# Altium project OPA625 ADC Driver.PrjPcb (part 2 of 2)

## Sheet OPA625 ADC Driver_OPA625 ADC Driver.SchDoc
size 762 x 381 mm; Date: Not shown in title block; ApprovedBy: Not shown in title block; CheckedBy: Not shown in title block; Author: Not shown in title block; CompanyName: Not shown in title block; Engineer: Not shown in title block; Organization: Not shown in title block; Address1: Not shown in title block; Address2: Not shown in title block; Address3: Not shown in title block; Address4: Not shown in title block; DocumentNumber: 5; Revision: Use project parameter SCH_Rev; SheetNumber: 5; SheetTotal: 8; PageSetup: Record=PageOptions¦CenterHorizontal=True¦CenterVertical=True¦PrintScale=1.00¦XCorrection=1.00¦YCorrection=1.00¦PrintKind=0¦BorderSize=5000000¦LeftOffset=0¦BottomOffset=0¦Orientation=2¦PaperLength=1000¦PaperWidth=1000¦Scale=100¦PaperSource=15¦PrintQuality=600¦MediaType=1¦DitherType=10¦PaperKind=Letter¦PrintScaleMode=1
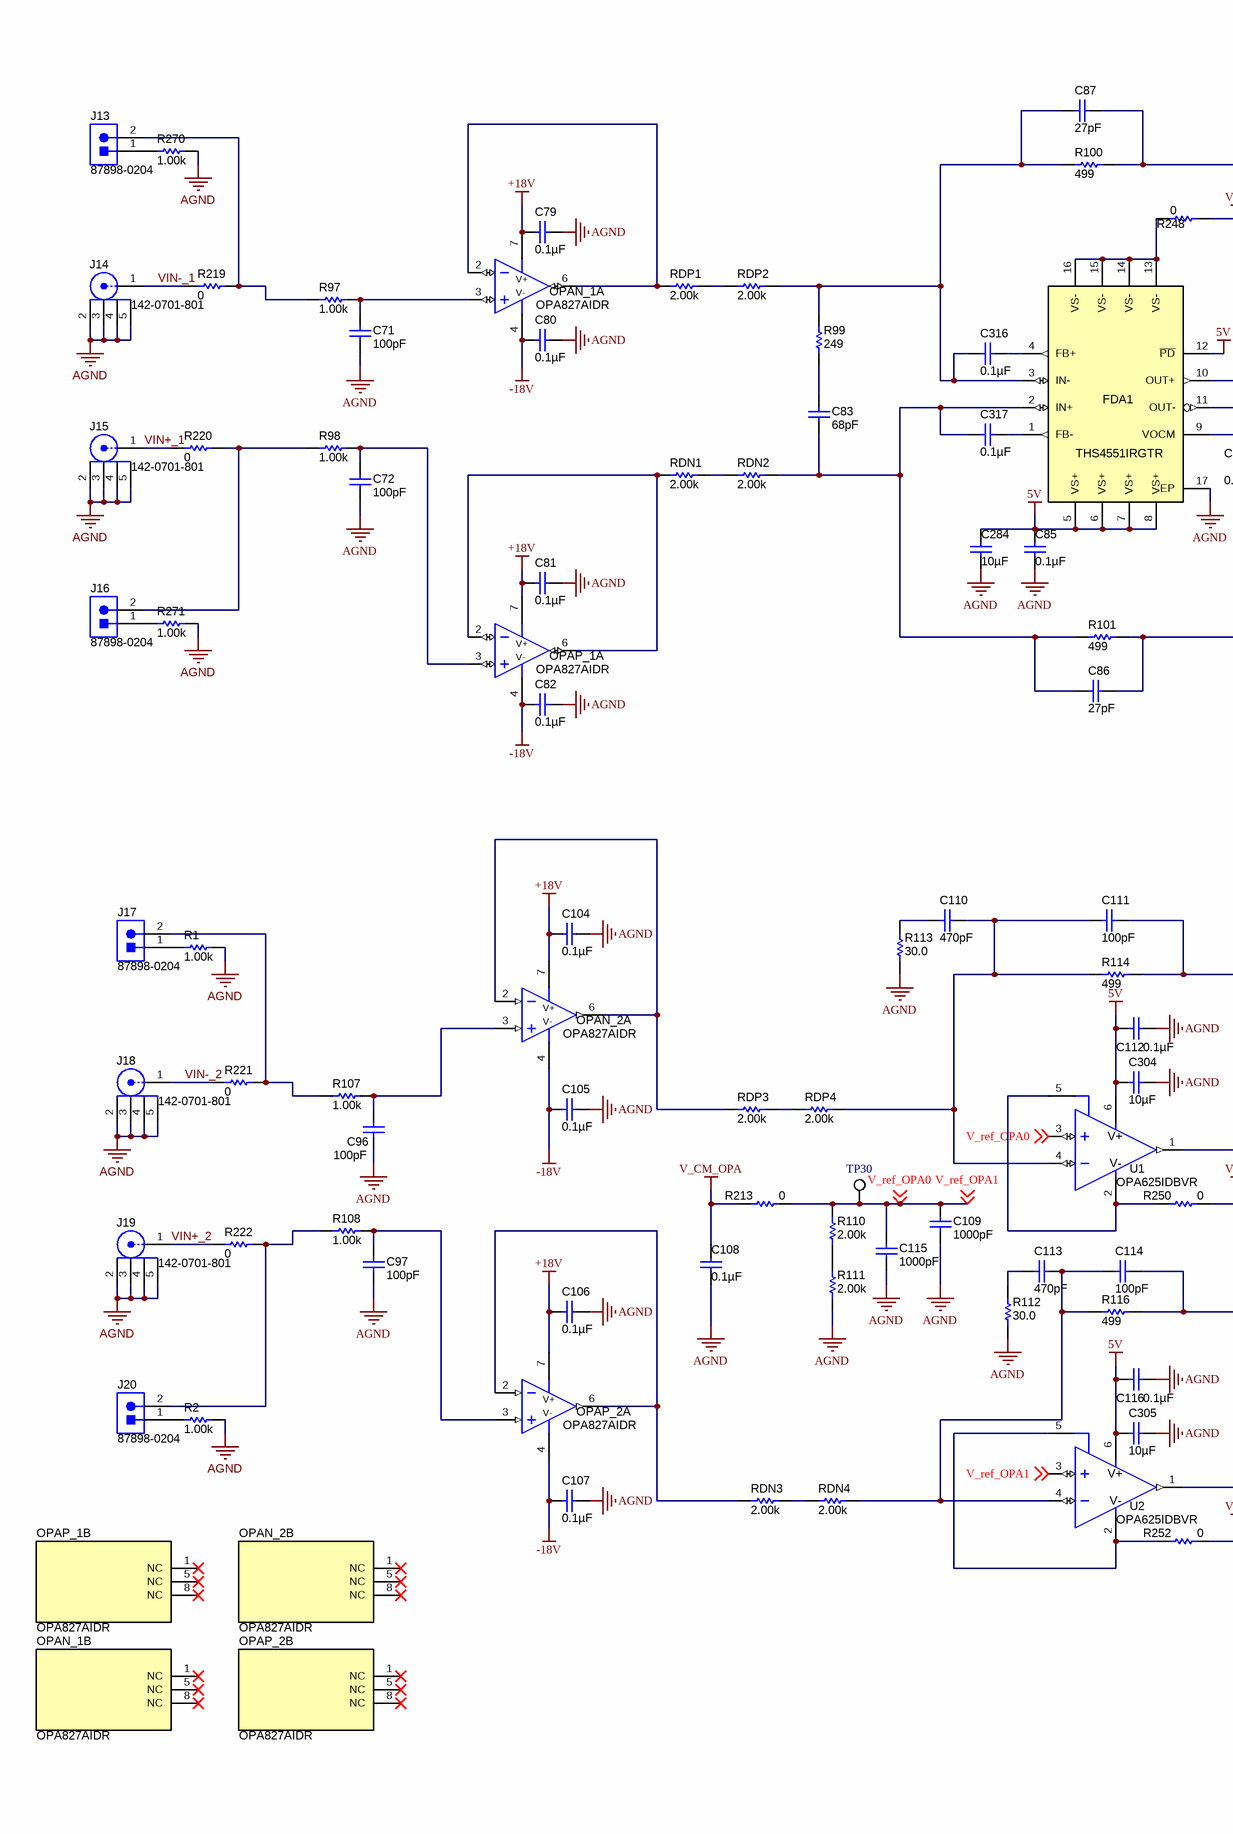
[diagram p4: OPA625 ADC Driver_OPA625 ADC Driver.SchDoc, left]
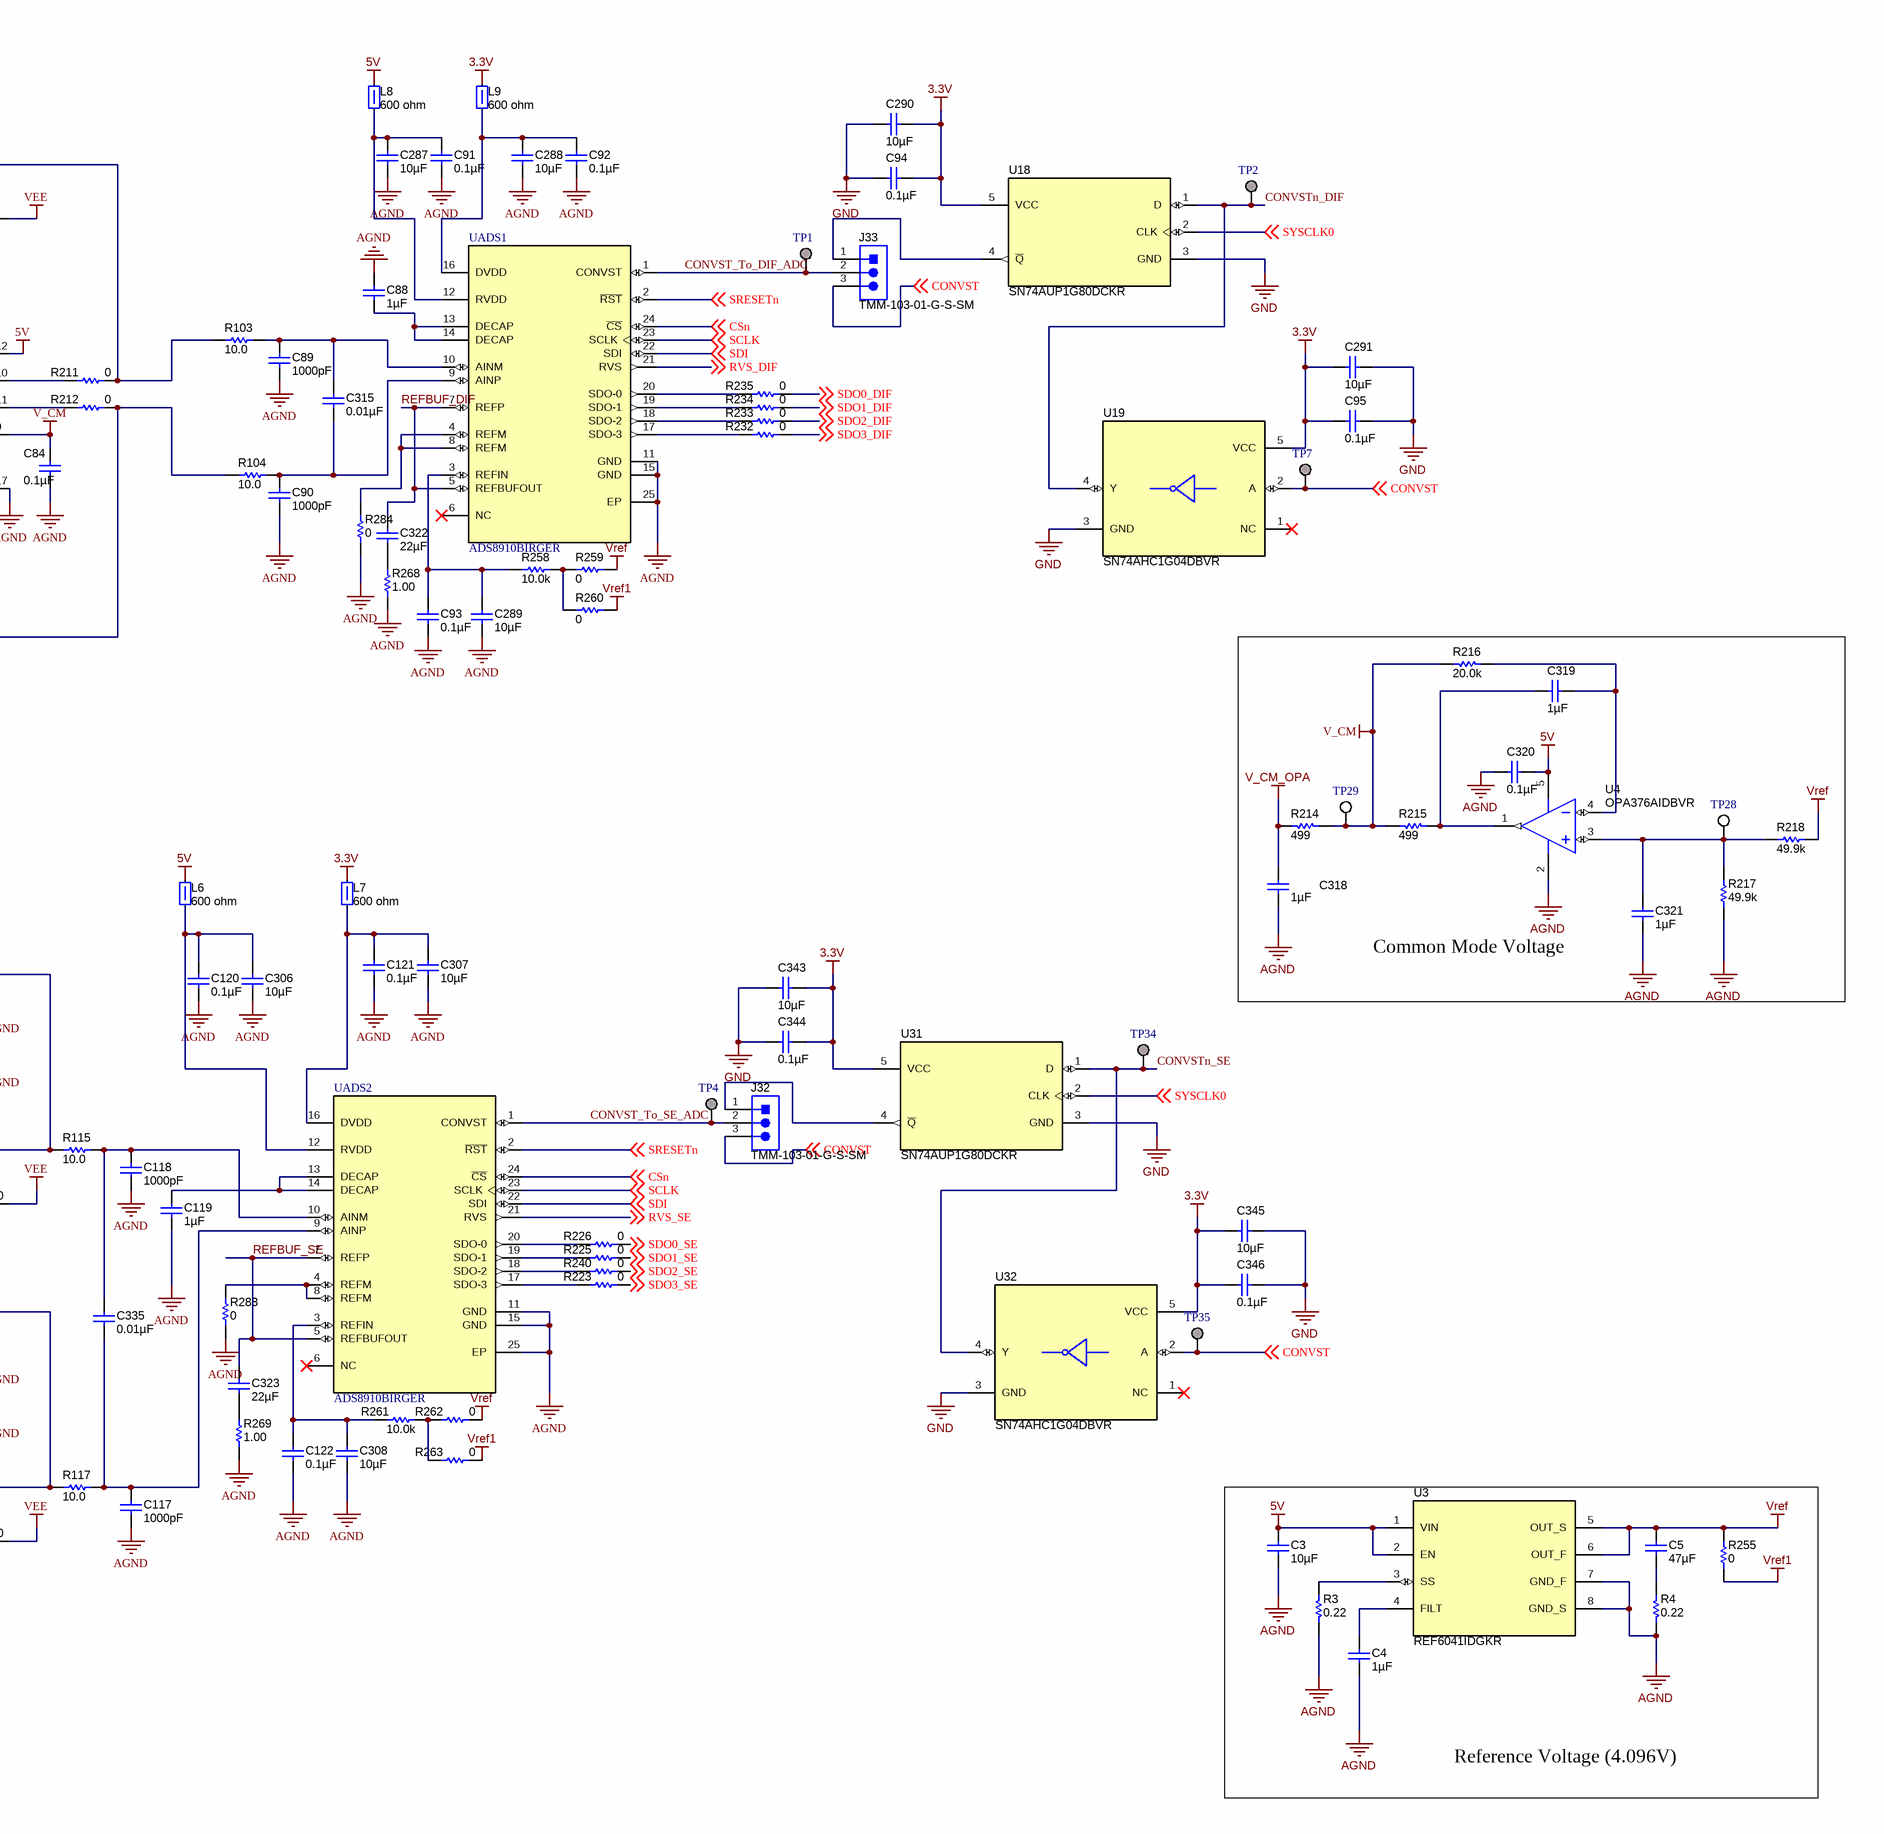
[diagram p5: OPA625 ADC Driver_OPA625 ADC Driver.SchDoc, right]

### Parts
C3  ValueDisplayed: 10µF  [0805]  (hidden comment: GRM21BR71A106KE51L)
C4  ValueDisplayed: 1µF  [0603]  (hidden comment: GRM188R71A105KA61D)
C5  ValueDisplayed: 47µF  [1210_270]  (hidden comment: GRM32ER71A476KE15L)
C71  ValueDisplayed: 100pF  [0603]  (hidden comment: GRM1885C1H101JA01D)
C72  ValueDisplayed: 100pF  [0603]  (hidden comment: GRM1885C1H101JA01D)
C79  ValueDisplayed: 0.1µF  [0603]  (hidden comment: GRM188R72A104KA35D)
C80  ValueDisplayed: 0.1µF  [0603]  (hidden comment: GRM188R72A104KA35D)
C81  ValueDisplayed: 0.1µF  [0603]  (hidden comment: GRM188R72A104KA35D)
C82  ValueDisplayed: 0.1µF  [0603]  (hidden comment: GRM188R72A104KA35D)
C83  ValueDisplayed: 68pF  [0603]  (hidden comment: C0603C680J5GACTU)
C84  ValueDisplayed: 0.1µF  [0603]  (hidden comment: C0603C104J3RACTU)
C85  ValueDisplayed: 0.1µF  [0603]  (hidden comment: C0603C104J3RACTU)
C86  ValueDisplayed: 27pF  [0603]  (hidden comment: C0603C270J5GACTU)
C87  ValueDisplayed: 27pF  [0603]  (hidden comment: C0603C270J5GACTU)
C88  ValueDisplayed: 1µF  [0603]  (hidden comment: GRM188R71A105KA61D)
C89  ValueDisplayed: 1000pF  [0603]  (hidden comment: C1608C0G2A102J080AA)
C90  ValueDisplayed: 1000pF  [0603]  (hidden comment: C1608C0G2A102J080AA)
C91  ValueDisplayed: 0.1µF  [0603]  (hidden comment: C0603C104J3RACTU)
C92  ValueDisplayed: 0.1µF  [0603]  (hidden comment: C0603C104J3RACTU)
C93  ValueDisplayed: 0.1µF  [0603]  (hidden comment: C0603C104J3RACTU)
C94  ValueDisplayed: 0.1µF  [0402]  (hidden comment: GRM155R71C104KA88D)
C95  ValueDisplayed: 0.1µF  [0402]  (hidden comment: GRM155R71C104KA88D)
C96  ValueDisplayed: 100pF  [0603]  (hidden comment: GRM1885C1H101JA01D)
C97  ValueDisplayed: 100pF  [0603]  (hidden comment: GRM1885C1H101JA01D)
C104  ValueDisplayed: 0.1µF  [0603]  (hidden comment: GRM188R72A104KA35D)
C105  ValueDisplayed: 0.1µF  [0603]  (hidden comment: GRM188R72A104KA35D)
C106  ValueDisplayed: 0.1µF  [0603]  (hidden comment: GRM188R72A104KA35D)
C107  ValueDisplayed: 0.1µF  [0603]  (hidden comment: GRM188R72A104KA35D)
C108  ValueDisplayed: 0.1µF  [0603]  (hidden comment: C0603C104J3RACTU)
C109  ValueDisplayed: 1000pF  [0603]  (hidden comment: C0603C102J5GAC)
C110  ValueDisplayed: 470pF  [0603]  (hidden comment: C0603C471K5RACTU)
C111  ValueDisplayed: 100pF  [0603]  (hidden comment: C0603C101J5GAC)
C112  ValueDisplayed: 0.1µF  [0603]  (hidden comment: C0603C104J3RACTU)
C113  ValueDisplayed: 470pF  [0603]  (hidden comment: C0603C471K5RACTU)
C114  ValueDisplayed: 100pF  [0603]  (hidden comment: C0603C101J5GAC)
C115  ValueDisplayed: 1000pF  [0603]  (hidden comment: C0603C102J5GAC)
C116  ValueDisplayed: 0.1µF  [0603]  (hidden comment: C0603C104J3RACTU)
C117  ValueDisplayed: 1000pF  [0603]  (hidden comment: C1608C0G2A102J080AA)
C118  ValueDisplayed: 1000pF  [0603]  (hidden comment: C1608C0G2A102J080AA)
C119  ValueDisplayed: 1µF  [0603]  (hidden comment: GRM188R71A105KA61D)
C120  ValueDisplayed: 0.1µF  [0603]  (hidden comment: C0603C104J3RACTU)
C121  ValueDisplayed: 0.1µF  [0603]  (hidden comment: C0603C104J3RACTU)
C122  ValueDisplayed: 0.1µF  [0603]  (hidden comment: C0603C104J3RACTU)
C284  ValueDisplayed: 10µF  [0805_HV]  (hidden comment: GRM21BR71A106KE51L)
C287  ValueDisplayed: 10µF  [0805_HV]  (hidden comment: GRM21BR71A106KE51L)
C288  ValueDisplayed: 10µF  [0805_HV]  (hidden comment: GRM21BR71A106KE51L)
C289  ValueDisplayed: 10µF  [0805_HV]  (hidden comment: GRM21BR71A106KE51L)
C290  ValueDisplayed: 10µF  [0805_HV]  (hidden comment: GRM21BR71A106KE51L)
C291  ValueDisplayed: 10µF  [0805_HV]  (hidden comment: GRM21BR71A106KE51L)
C304  ValueDisplayed: 10µF  [0805_HV]  (hidden comment: GRM21BR71A106KE51L)
C305  ValueDisplayed: 10µF  [0805_HV]  (hidden comment: GRM21BR71A106KE51L)
C306  ValueDisplayed: 10µF  [0805_HV]  (hidden comment: GRM21BR71A106KE51L)
C307  ValueDisplayed: 10µF  [0805_HV]  (hidden comment: GRM21BR71A106KE51L)
C308  ValueDisplayed: 10µF  [0805_HV]  (hidden comment: GRM21BR71A106KE51L)
C315  ValueDisplayed: 0.01µF  [0603]  (hidden comment: CGA3E2C0G1H103J080AA)
C316  ValueDisplayed: 0.1µF  [0603]  (hidden comment: C0603C104J3RACTU)
C317  ValueDisplayed: 0.1µF  [0603]  (hidden comment: C0603C104J3RACTU)
C318  ValueDisplayed: 1µF  [0603]  (hidden comment: GRM188R71E105KA12D)
C319  ValueDisplayed: 1µF  [0603]  (hidden comment: GRM188R71E105KA12D)
C320  ValueDisplayed: 0.1µF  [0603]  (hidden comment: C0603C104J3RACTU)
C321  ValueDisplayed: 1µF  [0603]  (hidden comment: GRM188R71E105KA12D)
C322  ValueDisplayed: 22µF  [0603]  (hidden comment: C1608X5R1A226M080AC)
C323  ValueDisplayed: 22µF  [0603]  (hidden comment: C1608X5R1A226M080AC)
C335  ValueDisplayed: 0.01µF  [0603]  (hidden comment: CGA3E2C0G1H103J080AA)
C343  ValueDisplayed: 10µF  [0805_HV]  (hidden comment: GRM21BR71A106KE51L)
C344  ValueDisplayed: 0.1µF  [0402]  (hidden comment: GRM155R71C104KA88D)
C345  ValueDisplayed: 10µF  [0805_HV]  (hidden comment: GRM21BR71A106KE51L)
C346  ValueDisplayed: 0.1µF  [0402]  (hidden comment: GRM155R71C104KA88D)
FDA1  THS4551IRGTR  [RGT0016A]
J13  87898-0204  [Molex_87898-0204]
J14  142-0701-801  [JOHNSON_142-0701-801]
J15  142-0701-801  [JOHNSON_142-0701-801]
J16  87898-0204  [Molex_87898-0204]
J17  87898-0204  [Molex_87898-0204]
J18  142-0701-801  [JOHNSON_142-0701-801]
J19  142-0701-801  [JOHNSON_142-0701-801]
J20  87898-0204  [Molex_87898-0204]
J32  TMM-103-01-G-S-SM  [Samtec_TMM-103-01-x-S-SM]
J33  TMM-103-01-G-S-SM  [Samtec_TMM-103-01-x-S-SM]
L6  value 600 ohm  [0805_HV]  (hidden comment: MPZ2012S601A)
L7  value 600 ohm  [0805_HV]  (hidden comment: MPZ2012S601A)
L8  value 600 ohm  [0805_HV]  (hidden comment: MPZ2012S601A)
L9  value 600 ohm  [0805_HV]  (hidden comment: MPZ2012S601A)
OPAN_1  OPA827AIDR  [D0008A_N]  (parts A,B of 2)
OPAN_2  OPA827AIDR  [D0008A_N]  (parts A,B of 2)
OPAP_1  OPA827AIDR  [D0008A_N]  (parts A,B of 2)
OPAP_2  OPA827AIDR  [D0008A_N]  (parts A,B of 2)
R1  ValueDisplayed: 1.00k  [0603]  (hidden comment: RG1608P-102-B-T5)
R2  ValueDisplayed: 1.00k  [0603]  (hidden comment: RG1608P-102-B-T5)
R3  value 0.22  [0603]  (hidden comment: ERJ-3RQFR22V)
R4  value 0.22  [0603]  (hidden comment: ERJ-3RQFR22V)
R97  ValueDisplayed: 1.00k  [0603]  (hidden comment: RG1608P-102-B-T5)
R98  ValueDisplayed: 1.00k  [0603]  (hidden comment: RG1608P-102-B-T5)
R99  ValueDisplayed: 249  [0603]  (hidden comment: CRCW0603249RFKEA)
R100  ValueDisplayed: 499  [0603]  (hidden comment: RC0603FR-07499RL)
R101  ValueDisplayed: 499  [0603]  (hidden comment: RC0603FR-07499RL)
R103  ValueDisplayed: 10.0  [0603]  (hidden comment: RT0603BRD0710RL)
R104  ValueDisplayed: 10.0  [0603]  (hidden comment: RT0603BRD0710RL)
R107  ValueDisplayed: 1.00k  [0603]  (hidden comment: RG1608P-102-B-T5)
R108  ValueDisplayed: 1.00k  [0603]  (hidden comment: RG1608P-102-B-T5)
R110  ValueDisplayed: 2.00k  [0603]  (hidden comment: RG1608P-202-B-T5)
R111  ValueDisplayed: 2.00k  [0603]  (hidden comment: RG1608P-202-B-T5)
R112  ValueDisplayed: 30.0  [0603]  (hidden comment: RC0603FR-0730RL)
R113  ValueDisplayed: 30.0  [0603]  (hidden comment: RC0603FR-0730RL)
R114  ValueDisplayed: 499  [0603]  (hidden comment: RC0603FR-07499RL)
R115  ValueDisplayed: 10.0  [0603]  (hidden comment: RT0603BRD0710RL)
R116  ValueDisplayed: 499  [0603]  (hidden comment: RC0603FR-07499RL)
R117  ValueDisplayed: 10.0  [0603]  (hidden comment: RT0603BRD0710RL)
R211  ValueDisplayed: 0  [0402]  (hidden comment: ERJ-2GE0R00X)
R212  ValueDisplayed: 0  [0402]  (hidden comment: ERJ-2GE0R00X)
R213  ValueDisplayed: 0  [0402]  (hidden comment: ERJ-2GE0R00X)
R214  ValueDisplayed: 499  [0603]  (hidden comment: RG1608P-4990-B-T5)
R215  ValueDisplayed: 499  [0603]  (hidden comment: RG1608P-4990-B-T5)
R216  ValueDisplayed: 20.0k  [0603]  (hidden comment: RG1608P-203-B-T5)
R217  ValueDisplayed: 49.9k  [0603]  (hidden comment: RG1608P-4992-B-T5)
R218  ValueDisplayed: 49.9k  [0603]  (hidden comment: RG1608P-4992-B-T5)
R219  ValueDisplayed: 0  [0603]  (hidden comment: ERJ-3GEY0R00V)
R220  ValueDisplayed: 0  [0603]  (hidden comment: ERJ-3GEY0R00V)
R221  ValueDisplayed: 0  [0603]  (hidden comment: ERJ-3GEY0R00V)
R222  ValueDisplayed: 0  [0603]  (hidden comment: ERJ-3GEY0R00V)
R223  ValueDisplayed: 0  [0402]  (hidden comment: ERJ-2GE0R00X)
R225  ValueDisplayed: 0  [0402]  (hidden comment: ERJ-2GE0R00X)
R226  ValueDisplayed: 0  [0402]  (hidden comment: ERJ-2GE0R00X)
R232  ValueDisplayed: 0  [0402]  (hidden comment: ERJ-2GE0R00X)
R233  ValueDisplayed: 0  [0402]  (hidden comment: ERJ-2GE0R00X)
R234  ValueDisplayed: 0  [0402]  (hidden comment: ERJ-2GE0R00X)
R235  ValueDisplayed: 0  [0402]  (hidden comment: ERJ-2GE0R00X)
R240  ValueDisplayed: 0  [0402]  (hidden comment: ERJ-2GE0R00X)
R248  ValueDisplayed: 0  [0402]  (hidden comment: ERJ-2GE0R00X)
R250  ValueDisplayed: 0  [0402]  (hidden comment: ERJ-2GE0R00X)
R252  ValueDisplayed: 0  [0402]  (hidden comment: ERJ-2GE0R00X)
R255  ValueDisplayed: 0  [0402]  (hidden comment: ERJ-2GE0R00X)
R258  ValueDisplayed: 10.0k  [0603]  (hidden comment: RG1608P-103-B-T5)
R259  ValueDisplayed: 0  [0402]  (hidden comment: ERJ-2GE0R00X)
R260  ValueDisplayed: 0  [0402]  (hidden comment: ERJ-2GE0R00X)
R261  ValueDisplayed: 10.0k  [0603]  (hidden comment: RG1608P-103-B-T5)
R262  ValueDisplayed: 0  [0402]  (hidden comment: ERJ-2GE0R00X)
R263  ValueDisplayed: 0  [0402]  (hidden comment: ERJ-2GE0R00X)
R268  ValueDisplayed: 1.00  [0603]  (hidden comment: CRCW06031R00FKEA)
R269  ValueDisplayed: 1.00  [0603]  (hidden comment: CRCW06031R00FKEA)
R270  ValueDisplayed: 1.00k  [0603]  (hidden comment: RG1608P-102-B-T5)
R271  ValueDisplayed: 1.00k  [0603]  (hidden comment: RG1608P-102-B-T5)
R284  ValueDisplayed: 0  [0402]  (hidden comment: ERJ-2GE0R00X)
R288  ValueDisplayed: 0  [0402]  (hidden comment: ERJ-2GE0R00X)
RDN1  ValueDisplayed: 2.00k  [0603]  (hidden comment: RG1608P-202-B-T5)
RDN2  ValueDisplayed: 2.00k  [0603]  (hidden comment: RG1608P-202-B-T5)
RDN3  ValueDisplayed: 2.00k  [0603]  (hidden comment: RG1608P-202-B-T5)
RDN4  ValueDisplayed: 2.00k  [0603]  (hidden comment: RG1608P-202-B-T5)
RDP1  ValueDisplayed: 2.00k  [0603]  (hidden comment: RG1608P-202-B-T5)
RDP2  ValueDisplayed: 2.00k  [0603]  (hidden comment: RG1608P-202-B-T5)
RDP3  ValueDisplayed: 2.00k  [0603]  (hidden comment: RG1608P-202-B-T5)
RDP4  ValueDisplayed: 2.00k  [0603]  (hidden comment: RG1608P-202-B-T5)
TP1  Pogo Pad  [PogoPad]  (value not drawn)  (no BOM)
TP2  Pogo Pad  [PogoPad]  (value not drawn)  (no BOM)
TP4  Pogo Pad  [PogoPad]  (value not drawn)  (no BOM)
TP7  Pogo Pad  [PogoPad]  (value not drawn)  (no BOM)
TP28  5015  [Testpoint_Keystone_Miniature]  (value not drawn)
TP29  5015  [Testpoint_Keystone_Miniature]  (value not drawn)
TP30  5015  [Testpoint_Keystone_Miniature]  (value not drawn)
TP34  Pogo Pad  [PogoPad]  (value not drawn)  (no BOM)
TP35  Pogo Pad  [PogoPad]  (value not drawn)  (no BOM)
U1  OPA625IDBVR  [DBV0006A_N]
U2  OPA625IDBVR  [DBV0006A_N]
U3  REF6041IDGKR  [DGK0008A_N]
U4  OPA376AIDBVR  [DBV0005A_N]
U18  SN74AUP1G80DCKR  [DCK0005A_N]
U19  SN74AHC1G04DBVR  [DBV0005A_N]
U31  SN74AUP1G80DCKR  [DCK0005A_N]
U32  SN74AHC1G04DBVR  [DBV0005A_N]
UADS1  ADS8910BIRGER  [RGE0024H]
UADS2  ADS8910BIRGER  [RGE0024H]

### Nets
3.3V: C94.2 C95.2 C290.1 C291.2 C343.1 C344.2 C345.2 C346.2 L7.1 L9.1 U18.5(VCC) U19.5(VCC) U31.5(VCC) U32.5(VCC)
5V: C3.2 C85.1 C112.2 C116.2 C284.1 C304.1 C305.1 C320.2 FDA1.5(VS+) FDA1.6(VS+) FDA1.7(VS+) FDA1.8(VS+) FDA1.12(~{PD}) L6.1 L8.1 U1.6(V+) U2.6(V+) U3.1(VIN) U3.2(EN) U4.5(V+)
+18V: C79.2 C81.2 C104.2 C106.2 OPAN_1.7(V+) OPAN_2.7(V+) OPAP_1.7(V+) OPAP_2.7(V+)
-18V: C80.2 C82.2 C105.2 C107.2 OPAN_1.4(V-) OPAN_2.4(V-) OPAP_1.4(V-) OPAP_2.4(V-)
AGND: C3.1 C4.2 C71.1 C72.1 C79.1 C80.1 C81.1 C82.1 C84.2 C85.2 C88.1 C89.2 C90.2 C91.1 C92.2 C93.2 C96.1 C97.1 C104.1 C105.1 C106.1 C107.1 C108.2 C109.2 C112.1 C115.2 C116.1 C117.2 C118.2 C119.2 C120.1 C121.2 C122.2 C284.2 C287.2 C288.2 C289.2 C304.2 C305.2 C306.2 C307.2 C308.2 C318.2 C320.1 C321.2 FDA1.17(EP) J14.2 J14.3 J14.4 J14.5 J15.2 J15.3 J15.4 J15.5 J18.2 J18.3 J18.4 J18.5 J19.2 J19.3 J19.4 J19.5 R1.2 R2.2 R3.1 R4.2 R111.1 R112.1 R113.1 R217.1 R268.1 R269.1 R270.2 R271.2 R284.1 R288.1 U3.7(GND_F) U3.8(GND_S) U4.2(V-) UADS1.11(GND) UADS1.15(GND) UADS1.25(EP) UADS2.11(GND) UADS2.15(GND) UADS2.25(EP)
GND: C94.1 C95.1 C290.2 C291.1 C343.2 C344.1 C345.1 C346.1 U18.3(GND) U19.3(GND) U31.3(GND) U32.3(GND)
V_CM: C84.1 FDA1.9(VOCM) R214.1 R215.2 R216.2 TP29.1
V_CM_OPA: C108.1 C318.1 R213.1 R214.2
VEE: R248.2 R250.2 R252.2
Vref: C5.1 R218.2 R255.2 R259.1 R262.2 U3.5(OUT_S) U3.6(OUT_F)
Vref1: R255.1 R260.1 R263.2
CONVST: J32.3 J33.3 TP7.1 TP35.1 U19.2(A) U32.2(A) ; off-sheet CONVST
CONVST_To_DIF_ADC: J33.2 TP1.1 UADS1.1(CONVST)
CONVST_To_SE_ADC: J32.2 TP4.1 UADS2.1(CONVST)
CONVSTn_DIF: TP2.1 U18.1(D) U19.4(Y)
CONVSTn_SE: TP34.1 U31.1(D) U32.4(Y)
CSn: UADS1.24(~{CS}) UADS2.24(~{CS}) ; off-sheet CSn
REFBUF_DIF: C322.1 UADS1.5(REFBUFOUT) UADS1.7(REFP)
REFBUF_SE: C323.1 UADS2.5(REFBUFOUT) UADS2.7(REFP)
RVS_DIF: UADS1.21(RVS) ; off-sheet RVS_DIF
RVS_SE: UADS2.21(RVS) ; off-sheet RVS_SE
SCLK: UADS1.23(SCLK) UADS2.23(SCLK) ; off-sheet SCLK
SDI: UADS1.22(SDI) UADS2.22(SDI) ; off-sheet SDI
SDO0_DIF: R235.2 ; off-sheet SDO0_DIF
SDO0_SE: R226.2 ; off-sheet SDO0_SE
SDO1_DIF: R234.2 ; off-sheet SDO1_DIF
SDO1_SE: R225.2 ; off-sheet SDO1_SE
SDO2_DIF: R233.2 ; off-sheet SDO2_DIF
SDO2_SE: R240.2 ; off-sheet SDO2_SE
SDO3_DIF: R232.2 ; off-sheet SDO3_DIF
SDO3_SE: R223.2 ; off-sheet SDO3_SE
SRESETn: UADS1.2(~{RST}) UADS2.2(~{RST}) ; off-sheet SRESETn
SYSCLK0: U18.2(CLK) U31.2(CLK) ; off-sheet SYSCLK0
V_ref_OPA0: C109.1 C115.1 R110.2 R213.2 TP30.1 U1.3(IN+) U2.3(IN+) ; off-sheet V_ref_OPA0, off-sheet V_ref_OPA1  [also labelled V_ref_OPA1]
VIN+_1: J15.1 R220.1
VIN+_2: J19.1 R222.1
VIN-_1: J14.1 R219.1
VIN-_2: J18.1 R221.1
NetC4_1: C4.1 U3.4(FILT)
NetC5_2: C5.2 R4.1
NetC71_2: C71.2 OPAN_1.3(IN+) R97.2
NetC72_2: C72.2 OPAP_1.3(IN+) R98.2
NetC83_1: C83.1 R99.1
NetC83_2: C83.2 C86.2 C317.2 FDA1.2(IN+) R101.1 RDN2.2
NetC86_1: C86.1 R101.2 R104.1 R212.2
NetC87_1: C87.1 R100.2 R103.1 R211.2
NetC87_2: C87.2 C316.2 FDA1.3(IN-) R99.2 R100.1 RDP2.2
NetC88_2: C88.2 UADS1.13(DECAP) UADS1.14(DECAP)
NetC89_1: C89.1 C315.1 R103.2 UADS1.10(AINM)
NetC90_1: C90.1 C315.2 R104.2 UADS1.9(AINP)
NetC91_2: C91.2 C287.1 L8.2 UADS1.12(RVDD)
NetC92_1: C92.1 C288.1 L9.2 UADS1.16(DVDD)
NetC93_1: C93.1 C289.1 R258.1 UADS1.3(REFIN)
NetC96_2: C96.2 OPAN_2.3(IN+) R107.2
NetC97_2: C97.2 OPAP_2.3(IN+) R108.2
NetC110_1: C110.1 R113.2
NetC110_2: C110.2 C111.2 R114.1 RDP4.2 U1.4(IN-)
NetC111_1: C111.1 R114.2 R115.1 U1.1(OUT)
NetC113_1: C113.1 C114.2 R116.1 RDN4.2 U2.4(IN-)
NetC113_2: C113.2 R112.2
NetC114_1: C114.1 R116.2 R117.1 U2.1(OUT)
NetC117_1: C117.1 C335.2 R117.2 UADS2.9(AINP)
NetC118_1: C118.1 C335.1 R115.2 UADS2.10(AINM)
NetC119_1: C119.1 UADS2.13(DECAP) UADS2.14(DECAP)
NetC120_2: C120.2 C306.1 L6.2 UADS2.12(RVDD)
NetC121_1: C121.1 C307.1 L7.2 UADS2.16(DVDD)
NetC122_1: C122.1 C308.1 R261.1 UADS2.3(REFIN)
NetC316_1: C316.1 FDA1.4(FB+)
NetC317_1: C317.1 FDA1.1(FB-)
NetC319_1: C319.1 R215.1 U4.1(OUT)
NetC319_2: C319.2 R216.1 U4.4(IN-)
NetC321_1: C321.1 R217.2 R218.1 TP28.1 U4.3(IN+)
NetC322_2: C322.2 R268.2
NetC323_2: C323.2 R269.2
NetFDA1_10: FDA1.10(OUT+) R211.1
NetFDA1_11: FDA1.11(OUT-) R212.1
NetFDA1_13: FDA1.13(VS-) FDA1.14(VS-) FDA1.15(VS-) FDA1.16(VS-) R248.1
NetJ13_1: J13.1 R270.1
NetJ13_2: J13.2 R97.1 R219.2
NetJ16_1: J16.1 R271.1
NetJ16_2: J16.2 R98.1 R220.2
NetJ17_1: J17.1 R1.1
NetJ17_2: J17.2 R107.1 R221.2
NetJ20_1: J20.1 R2.1
NetJ20_2: J20.2 R108.1 R222.2
NetJ32_1: J32.1 U31.4(~{Q})
NetJ33_1: J33.1 U18.4(~{Q})
NetOPAN_1_2: OPAN_1.2(IN-) OPAN_1.6(OUT) RDP1.1
NetOPAN_2_2: OPAN_2.2(IN-) OPAN_2.6(OUT) RDP3.1
NetOPAP_1_2: OPAP_1.2(IN-) OPAP_1.6(OUT) RDN1.1
NetOPAP_2_2: OPAP_2.2(IN-) OPAP_2.6(OUT) RDN3.1
NetR3_2: R3.2 U3.3(SS)
NetR110_1: R110.1 R111.2
NetR223_1: R223.1 UADS2.17(SDO-3)
NetR225_1: R225.1 UADS2.19(SDO-1)
NetR226_1: R226.1 UADS2.20(SDO-0)
NetR232_1: R232.1 UADS1.17(SDO-3)
NetR233_1: R233.1 UADS1.18(SDO-2)
NetR234_1: R234.1 UADS1.19(SDO-1)
NetR235_1: R235.1 UADS1.20(SDO-0)
NetR240_1: R240.1 UADS2.18(SDO-2)
NetR250_1: R250.1 U1.2(V-) U1.5(MODE)
NetR252_1: R252.1 U2.2(V-) U2.5(MODE)
NetR258_2: R258.2 R259.2 R260.2
NetR261_2: R261.2 R262.1 R263.1
NetR284_2: R284.2 UADS1.4(REFM) UADS1.8(REFM)
NetR288_2: R288.2 UADS2.4(REFM) UADS2.8(REFM)
NetRDN1_2: RDN1.2 RDN2.1
NetRDN3_2: RDN3.2 RDN4.1
NetRDP1_2: RDP1.2 RDP2.1
NetRDP3_2: RDP3.2 RDP4.1

Not connected (* = marked no-connect by the designer): OPAN_1 1(NC)* 5(NC)* 8(NC)*; OPAN_2 1(NC)* 5(NC)* 8(NC)*; OPAP_1 1(NC)* 5(NC)* 8(NC)*; OPAP_2 1(NC)* 5(NC)* 8(NC)*; U19 1(NC)*; U32 1(NC)*; UADS1 6(NC)*; UADS2 6(NC)*

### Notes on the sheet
- Common Mode Voltage
- Reference Voltage (4.096V)

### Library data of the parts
C3 = GRM21BR71A106KE51L: CAP, CERM, 10uF, 10V, +/-10%, X7R, 0805; Manufacturer: MuRata; Polarized: N; CompType: Capacitor; U/M: EA; Cap_F: 0.00001; Tolerance_%: 10; ESR_Ohm: 0.003; Value1: 0.003 ohm; TaMin_C: -55; TaMax_C: 125
C4 = GRM188R71A105KA61D: CAP, CERM, 1uF, 10V, +/-10%, X7R, 0603; Manufacturer: MuRata; Polarized: N; CompType: Capacitor; U/M: EA; Cap_F: 0.000001; Tolerance_%: 10; ESR_Ohm: 0.011; Value1: 0.011 ohm; TaMin_C: -55; TaMax_C: 125
C5 = GRM32ER71A476KE15L: CAP, CERM, 47 µF, 10 V, +/- 10%, X7R, 1210; Manufacturer: MuRata; Polarized: N; CompType: Capacitor; Value: 47uF; U/M: EA; Cap_F: 0.000047; Tolerance_%: 10; Value1: Unknown; Value2: 10V; TaMin_C: -55; TaMax_C: 125; Cap_Case: 1210; SizeArea_mm2: 8; SizeAreaWB_mm2: 14.7; SizeX_mm: 3.2; SizeY_mm: 2.5; SizeZ_mm: 2.7; AEC Category: Q200
C71 C72 C96 C97 = GRM1885C1H101JA01D: CAP, CERM, 100 pF, 50 V, +/- 5%, C0G/NP0, 0603; Manufacturer: MuRata; Polarized: N; CompType: Capacitor; Value: 100pF; U/M: EA; Cap_F: 0.0000000001; Tolerance_%: 5; Value1: Unknown; VDC_V: 50; Value2: 50V; TaMin_C: -55; TaMax_C: 125; AEC Category: Q200
C79-C82 C104-C107 = GRM188R72A104KA35D: CAP, CERM, 0.1 µF, 100 V, +/- 10%, X7R, 0603; Manufacturer: MuRata; Polarized: N; CompType: Capacitor; Value: 0.1uF; U/M: EA; Cap_F: 0.0000001; Tolerance_%: 10; Value1: Unknown; VDC_V: 100; Value2: 100V; TaMin_C: -55; TaMax_C: 125; SizeArea_mm2: 1.28; SizeAreaWB_mm2: 4.68; SizeX_mm: 1.6; SizeY_mm: 0.8; SizeZ_mm: 1; AEC Category: Q200
C83 = C0603C680J5GACTU: CAP, CERM, 68 pF, 50 V, +/- 5%, C0G/NP0, 0603; Manufacturer: Kemet; Polarized: N; CompType: Capacitor; Value: 68pF; U/M: EA; Cap_F: 0.000000000068; Tolerance_%: 5; Value1: Unknown; VDC_V: 50; Value2: 50V; TaMin_C: -55; TaMax_C: 125; SizeArea_mm2: 1.28; SizeAreaWB_mm2: 4.68; SizeX_mm: 1.6; SizeY_mm: 0.8; SizeZ_mm: 1; AEC Category: Q200
C84 C85 C91-C93 C108 C112 C116 C120-C122 C316 C317 = C0603C104J3RACTU: CAP, CERM, 0.1 µF, 25 V, +/- 5%, X7R, 0603; Manufacturer: Kemet; Polarized: N; CompType: Capacitor; Value: 0.1uF; U/M: EA; Cap_F: 0.0000001; Tolerance_%: 5; Value1: Unknown; VDC_V: 25; Value2: 25V; TaMin_C: -55; TaMax_C: 125
C86 C87 = C0603C270J5GACTU: CAP, CERM, 27 pF, 50 V, +/- 5%, C0G/NP0, 0603; Manufacturer: Kemet; Polarized: N; CompType: Capacitor; Value: 27pF; U/M: EA; Cap_F: 0.000000000027; Tolerance_%: 5; Value1: Unknown; VDC_V: 50; Value2: 50V; TaMin_C: -55; TaMax_C: 125; SizeArea_mm2: 1.28; SizeAreaWB_mm2: 4.68; SizeX_mm: 1.6; SizeY_mm: 0.8; SizeZ_mm: 1; AEC Category: Q200
C88 C119 = GRM188R71A105KA61D: CAP, CERM, 1 µF, 10 V, +/- 10%, X7R, 0603; Manufacturer: MuRata; Polarized: N; CompType: Capacitor; Value: 1uF; U/M: EA; Cap_F: 0.000001; Tolerance_%: 10; ESR_ohm: 0.011; Value1: 0.011 ohm; Value2: 10V; TaMin_C: -55; TaMax_C: 125; SizeArea_mm2: 1.28; SizeAreaWB_mm2: 4.68; SizeX_mm: 1.6; SizeY_mm: 0.8; SizeZ_mm: 1; AEC Category: Q200
C89 C90 C117 C118 = C1608C0G2A102J080AA: CAP, CERM, 1000 pF, 100 V, +/- 5%, C0G/NP0, 0603; Manufacturer: TDK; Polarized: N; CompType: Capacitor; Value: 1000pF; U/M: EA; Cap_F: 0.000000001; Tolerance_%: 5; ESR_ohm: 0.0589; Value1: 0.0589 ohm; VDC_V: 100; Value2: 100V; TaMin_C: -55; TaMax_C: 125; SizeArea_mm2: 1.28; SizeAreaWB_mm2: 4.68; SizeX_mm: 1.6; SizeY_mm: 0.8; SizeZ_mm: 1; AEC Category: Q200
C94 C95 C344 C346 = GRM155R71C104KA88D: CAP, CERM, 0.1 µF, 16 V, +/- 10%, X7R, 0402; Manufacturer: MuRata; Polarized: N; CompType: Capacitor; Value: 0.1uF; U/M: EA; Cap_F: 0.0000001; Tolerance_%: 10; Value1: Unknown; VDC_V: 16; Value2: 16V; TaMin_C: -55; TaMax_C: 125
C109 C115 = C0603C102J5GAC: CAP, CERM, 1000 pF, 50 V, +/- 5%, C0G/NP0, 0603; Manufacturer: Kemet; Polarized: N; CompType: Capacitor; Value: 1000pF; U/M: EA; Cap_F: 0.000000001; Tolerance_%: 5; Value1: Unknown; VDC_V: 50; Value2: 50V; TaMin_C: -55; TaMax_C: 125; SizeArea_mm2: 1.28; SizeAreaWB_mm2: 4.68; SizeX_mm: 1.6; SizeY_mm: 0.8; SizeZ_mm: 1; AEC Category: Q200
C110 C113 = C0603C471K5RACTU: CAP, CERM, 470 pF, 50 V, +/- 10%, X7R, 0603; Manufacturer: Kemet; Polarized: N; CompType: Capacitor; Value: 470pF; U/M: EA; Cap_F: 0.00000000047; Tolerance_%: 10; Value1: Unknown; VDC_V: 50; Value2: 50V; TaMin_C: -55; TaMax_C: 125; SizeArea_mm2: 1.28; SizeAreaWB_mm2: 4.68; SizeX_mm: 1.6; SizeY_mm: 0.8; SizeZ_mm: 1; AEC Category: Q200
C111 C114 = C0603C101J5GAC: CAP, CERM, 100 pF, 50 V, +/- 5%, C0G/NP0, 0603; Manufacturer: Kemet; Polarized: N; CompType: Capacitor; Value: 100pF; U/M: EA; Cap_F: 0.0000000001; Tolerance_%: 5; Value1: Unknown; VDC_V: 50; Value2: 50V; TaMin_C: -55; TaMax_C: 125; SizeArea_mm2: 1.28; SizeAreaWB_mm2: 4.68; SizeX_mm: 1.6; SizeY_mm: 0.8; SizeZ_mm: 1; AEC Category: Q200
C284 C287-C291 C304-C308 C343 C345 = GRM21BR71A106KE51L: CAP, CERM, 10 µF, 10 V, +/- 10%, X7R, 0805; Manufacturer: MuRata; Polarized: N; CompType: Capacitor; Value: 10uF; U/M: EA; Cap_F: 0.00001; Tolerance_%: 10; ESR_ohm: 0.003; Value1: 0.003 ohm; Value2: 10V; TaMin_C: -55; TaMax_C: 125; Cap_Case: 0805; AEC Category: Q200
C315 C335 = CGA3E2C0G1H103J080AA: CAP, CERM, 0.01 µF, 50 V, +/- 5%, C0G/NP0, AEC-Q200 Grade 1, 0603; Manufacturer: TDK; Polarized: N; CompType: Capacitor; Value: 0.01uF; U/M: EA; Cap_F: 0.00000001; Tolerance_%: 5; Value1: Unknown; VDC_V: 50; Value2: 50V; TaMin_C: -55; TaMax_C: 125; SizeArea_mm2: 1.28; SizeAreaWB_mm2: 4.68; SizeX_mm: 1.6; SizeY_mm: 0.8; SizeZ_mm: 1; AEC Category: Q200; AEC Qualified: Y
C318 C319 C321 = GRM188R71E105KA12D: CAP, CERM, 1 µF, 25 V, +/- 10%, X7R, 0603; Manufacturer: MuRata; Polarized: N; CompType: Capacitor; Value: 1uF; U/M: EA; Cap_F: 0.000001; Tolerance_%: 10; Value1: Unknown; VDC_V: 25; Value2: 25V; TaMin_C: -55; TaMax_C: 125; AEC Category: Q200
C320 = C0603C104J3RACTU: CAP, CERM, 0.1 µF, 25 V, +/- 5%, X7R, 0603; Manufacturer: Kemet; Polarized: N; CompType: Capacitor; Value: 0.1uF; U/M: EA; Cap_F: 0.0000001; Tolerance_%: 5; Value1: Unknown; VDC_V: 25; Value2: 25V; TaMin_C: -55; TaMax_C: 125; AEC Category: Q200
C322 C323 = C1608X5R1A226M080AC: CAP, CERM, 22 µF, 10 V, +/- 20%, X5R, 0603; Manufacturer: TDK; Polarized: N; CompType: Capacitor; Value: 22uF; U/M: EA; Cap_F: 0.000022; Tolerance_%: 20; ESR_ohm: 0.00371; Value1: 0.00371 ohm; VDC_V: 10; Value2: 10V; IRMS_A: 2.69936; TaMin_C: -55; TaMax_C: 85; SizeArea_mm2: 1.28; SizeAreaWB_mm2: 4.68; SizeX_mm: 1.6; SizeY_mm: 0.8; SizeZ_mm: 1; AEC Category: Q200
FDA1 = THS4551IRGTR: Low Power, Precision, 160MHz, Fully Differential Amplifier, RGT0016A; Alternate PartNumber: THS4551IRGTT; Manufacturer: Texas Instruments; SymbolCreator: Altium; SizeX_mm: 4; SizeZ_mm: 1; CompType: IC; U/M: EA
J13 J16 J17 J20 = 87898-0204: Header, 2.54 mm, 2x1, Gold, R/A, SMT; Manufacturer: Molex; SymbolCreator: a0412235; U/M: EA
J14 J15 J18 J19 = 142-0701-801: Connector, End launch SMA, 50 ohm, SMT; Manufacturer: Johnson; SymbolCreator: X0208326; U/M: EA
J32 J33 = TMM-103-01-G-S-SM: Header, 2mm, 3x1, Gold, SMT; Manufacturer: Samtec; SymbolCreator: a0799628; Pitch_mm: 2; Gender: Male; Shrouded: N; Row_Count: 1; Current_A: 3.2; Voltage_V: 500; Cert_CSA: Y
L6-L9 = MPZ2012S601A: Ferrite Bead, 600 ohm @ 100MHz, 2A, 0805; Manufacturer: TDK; Imax_A: 2; DCR_ohm: 0.1; Value1: 0.1 ohm; ZTyp@100MHz_Ohm: 600
OPAN_1 OPAP_1 = OPA827AIDR: Low-Noise, High-Precision, JFET-Input OPERATIONAL AMPLIFIER, D0008A; Manufacturer: Texas Instruments; SymbolCreator: a0411595/a0412235; CompType: IC; U/M: EA
OPAN_2 OPAP_2 = OPA827AIDR: Low-Noise, High-Precision, JFET-Input OPERATIONAL AMPLIFIER, D0008A; Manufacturer: Texas Instruments; SymbolCreator: a0411595/a0412235; SizeArea_mm2: 30.38; SizeAreaWB_mm2: 56.58; SizeX_mm: 4.9; SizeY_mm: 6.2; SizeZ_mm: 1.75; CompType: IC; U/M: EA
R1 R2 R97 R98 R107 R108 R270 R271 = RG1608P-102-B-T5: RES, 1.00 k, 0.1%, 0.1 W, 0603; Manufacturer: Susumu Co Ltd; CompType: Resistor; Value: 1.00k; Res_ohm: 1000; Value_Code: 1k00; Tolerance_%: 0.1; Value2: 0.1W; VDC_V: 75; TempCo: 25 ppm/C; EIA_Code: E192; U/M: EA
R3 R4 = ERJ-3RQFR22V: RES, 0.22 ohm, 1%, 0.1W, 0603; Manufacturer: Panasonic; CompType: Resistor; Value_Code: R220; Tolerance_%: 1; Power_W: 0.1; TempCo: 300 ppm/C; EIA_Code: E96; U/M: EA
R99 = CRCW0603249RFKEA: RES, 249, 1%, 0.1 W, 0603; Manufacturer: Vishay-Dale; CompType: Resistor; Value: 249; Value_Code: 249R; Tolerance_%: 1; Power_W: 0.1; Value2: 0.1W; VDC_V: 75; TempCo: 100 ppm/C; SizeArea_mm2: 1.28; SizeX_mm: 1.6; SizeY_mm: 0.8; EIA_Code: E96; U/M: EA; AEC Category: Q200
R100 R101 R114 R116 = RC0603FR-07499RL: RES, 499, 1%, 0.1 W, 0603; Manufacturer: Yageo America; CompType: Resistor; Value: 499; Value_Code: 499R; Tolerance_%: 1; Power_W: 0.1; Value2: 0.1W; VDC_V: 150; TempCo: 200 ppm/C; SizeArea_mm2: 1.28; SizeX_mm: 1.6; SizeY_mm: 0.8; EIA_Code: E96; U/M: EA; AEC Category: Q200
R103 R104 R115 R117 = RT0603BRD0710RL: RES, 10.0, 0.1%, 0.1 W, 0603; Manufacturer: Yageo America; CompType: Resistor; Value: 10.0; Res_ohm: 10; Value_Code: 10R0; Tolerance_%: 0.1; Value2: 0.1W; VDC_V: 75; TempCo: 25 ppm/C; SizeArea_mm2: 1.28; SizeX_mm: 1.6; SizeY_mm: 0.8; SizeZ_mm: 1; EIA_Code: E192; U/M: EA; AEC Category: Q200
R110 R111 RDN1-RDN4 RDP1-RDP4 = RG1608P-202-B-T5: RES, 2.00 k, 0.1%, 0.1 W, 0603; Manufacturer: Susumu Co Ltd; CompType: Resistor; Value: 2.00k; Res_ohm: 2000; Value_Code: 2k00; Tolerance_%: 0.1; Value2: 0.1W; VDC_V: 75; TempCo: 25 ppm/C; EIA_Code: E192; U/M: EA; AEC Category: Q200
R112 R113 = RC0603FR-0730RL: RES, 30.0, 1%, 0.1 W, 0603; Manufacturer: Yageo America; CompType: Resistor; Value: 30.0; Res_ohm: 30; Value_Code: 30R0; Tolerance_%: 1; Power_W: 0.1; Value2: 0.1W; VDC_V: 150; TempCo: 200 ppm/C; SizeArea_mm2: 1.28; SizeX_mm: 1.6; SizeY_mm: 0.8; U/M: EA; AEC Category: Q200
R211-R213 R223 R225 R226 R232-R235 R240 R248 R250 R252 R255 R259 R260 R262 R263 R284 R288 = ERJ-2GE0R00X: RES, 0, 5%, 0.063 W, 0402; Manufacturer: Panasonic; CompType: Resistor; Value: 0; Value_Code: 0000; Tolerance_%: 5; Power_W: 0.063; Value2: 0.063W; VDC_V: 50; TempCo: 600 ppm/C; EIA_Code: E24; U/M: EA; AEC Category: Q200
R214 R215 = RG1608P-4990-B-T5: RES, 499, 0.1%, 0.1 W, 0603; Manufacturer: Susumu Co Ltd; CompType: Resistor; Value: 499; Value_Code: 499R; Tolerance_%: 0.1; Value2: 0.1W; VDC_V: 75; TempCo: 25 ppm/C; EIA_Code: E192; U/M: EA; AEC Category: Q200
R216 = RG1608P-203-B-T5: RES, 20.0 k, 0.1%, 0.1 W, 0603; Manufacturer: Susumu Co Ltd; CompType: Resistor; Value: 20.0k; Res_ohm: 20000; Value_Code: 20k0; Tolerance_%: 0.1; Value2: 0.1W; VDC_V: 75; TempCo: 25 ppm/C; EIA_Code: E192; U/M: EA; AEC Category: Q200
R217 R218 = RG1608P-4992-B-T5: RES, 49.9 k, 0.1%, 0.1 W, 0603; Manufacturer: Susumu Co Ltd; CompType: Resistor; Value: 49.9k; Res_ohm: 49900; Value_Code: 49k9; Tolerance_%: 0.1; Value2: 0.1W; VDC_V: 75; TempCo: 25 ppm/C; EIA_Code: E192; U/M: EA; AEC Category: Q200
R219-R222 = ERJ-3GEY0R00V: RES, 0, 5%, 0.1 W, 0603; Manufacturer: Panasonic; CompType: Resistor; Value: 0; Value_Code: 0000; Tolerance_%: 5; Power_W: 0.1; Value2: 0.1W; VDC_V: 50; TempCo: 600 ppm/C; EIA_Code: E24; U/M: EA; AEC Category: Q200
R258 R261 = RG1608P-103-B-T5: RES, 10.0 k, 0.1%, 0.1 W, 0603; Manufacturer: Susumu Co Ltd; CompType: Resistor; Value: 10.0k; Res_ohm: 10000; Value_Code: 10k0; Tolerance_%: 0.1; Value2: 0.1W; VDC_V: 75; TempCo: 25 ppm/C; SizeArea_mm2: 1.28; SizeX_mm: 1.6; SizeY_mm: 0.8; SizeZ_mm: 1; EIA_Code: E192; U/M: EA; AEC Category: Q200
R268 R269 = CRCW06031R00FKEA: RES, 1.00, 1%, 0.1 W, 0603; Manufacturer: Vishay-Dale; CompType: Resistor; Value: 1.00; Res_ohm: 1; Value_Code: 1R00; Power_W: 0.1; Value2: 0.1W; VDC_V: 75; TempCo: 100 ppm/C; SizeArea_mm2: 1.28; SizeX_mm: 1.6; SizeY_mm: 0.8; EIA_Code: E96; U/M: EA; AEC Category: Q200
TP1 TP2 TP4 TP7 TP34 TP35 = PogoPad: Pad for Pogo Pin Connector; SymbolCreator: codlsc
TP28-TP30 = 5015: Test Point, Miniature, SMT; Manufacturer: Keystone; CompType: Test Point Loop
U1 U2 = OPA625IDBVR: High Bandwidth, High Precision, Low Noise and Distortion Amplifier with Ultra-Fast Transition time Low Power mode, DBV0006A; Alternate PartNumber: OPA625IDBVT; Manufacturer: Texas Instruments; SymbolCreator: Altium; SizeArea_mm2: 8.12; SizeAreaWB_mm2: 14.82; SizeX_mm: 2.8; SizeY_mm: 2.9; SizeZ_mm: 1.45; CompType: IC; U/M: EA
U3 = REF6041IDGKR: High-Precision Voltage Reference with Integrated High-Bandwidth Buffer, DGK0008A; Alternate PartNumber: REF6041IDGKT; Manufacturer: Texas Instruments; SymbolCreator: Altium; SizeArea_mm2: 15.655; SizeAreaWB_mm2: 35.955; SizeX_mm: 5.05; SizeY_mm: 3.1; SizeZ_mm: 1.1; CompType: IC; U/M: EA
U4 = OPA376AIDBVR: Precision, Low Noise, Low Iq Operational Amplifier, 2.2 to 5.5 V, -40 to 125 degC, 5-pin SOT23 (DBV0005A), Green (RoHS & no Sb/Br); Manufacturer: Texas Instruments; Alternate PartNumber: Equivalent; CMRR(Min)(dB): 76; IIB(Max)(pA): 10; Iq per channel(Max)(mA): 0.95; Number of Channels: 1; Offset Drift(Typ)(uV/C): 0.32; Slew Rate(Typ)(V/us): 2; Sub Family: Low Input Bias Current Amp (<=10pA), Low Noise Amp (<=10nV/rtHz), Low Offset Voltage Amplifier (<=500uV), Low Supply Voltage Amplifier (<=2.7V), Precision Amplifier; Total Supply Voltage(Max)(+5V is 5, +/-5V is 10): 5.5; Total Supply Voltage(Min)(+5V is 5, +/-5V is 10): 2.2; Vio (25C)(Max)(mV): 0.025; Vn at 1kHz(Typ)(nV/rtHz): 7.5
U18 U31 = SN74AUP1G80DCKR: LOW-POWER SINGLE POSITIVE-EDGE-TRIGGERED D-TYPE FLIP-FLOP, DCK0005A; Alternate PartNumber: SN74AUP1G80DCKT; Manufacturer: Texas Instruments; SymbolCreator: Altium; SizeArea_mm2: 4.2; SizeAreaWB_mm2: 9.3; SizeX_mm: 2.1; SizeY_mm: 2; SizeZ_mm: 1.1; CompType: IC; U/M: EA
U19 U32 = SN74AHC1G04DBVR: SINGLE SCHMITT-TRIGGER INVERTER GATE, DBV0005A; Alternate PartNumber: SN74AHC1G04DBVT; Manufacturer: Texas Instruments; SymbolCreator: a0411947; CompType: IC; U/M: EA
UADS1 UADS2 = ADS8910BIRGER: 18-Bit, 1-MSPS SAR ADC with Integrated Reference Buffer, LDO, and Enhanced Serial Interface, RGE0024H; Manufacturer: Texas Instruments; SymbolCreator: Altium; CompType: IC; U/M: EA

## Sheet OPA625 ADC Driver_Clock.SchDoc
size 431 x 279 mm; Date: Not shown in title block; ApprovedBy: Not shown in title block; CheckedBy: Not shown in title block; Author: Not shown in title block; CompanyName: Not shown in title block; Engineer: Not shown in title block; Organization: Not shown in title block; Address1: Not shown in title block; Address2: Not shown in title block; Address3: Not shown in title block; Address4: Not shown in title block; DocumentNumber: 7; Revision: Use project parameter SCH_Rev; SheetNumber: 7; SheetTotal: 8; PageSetup: Record=PageOptions¦CenterHorizontal=True¦CenterVertical=True¦PrintScale=1.00¦XCorrection=1.00¦YCorrection=1.00¦PrintKind=0¦BorderSize=5000000¦LeftOffset=0¦BottomOffset=0¦Orientation=2¦PaperLength=1000¦PaperWidth=1000¦Scale=100¦PaperSource=15¦PrintQuality=600¦MediaType=1¦DitherType=10¦PrintScaleMode=1¦PaperKind=Letter
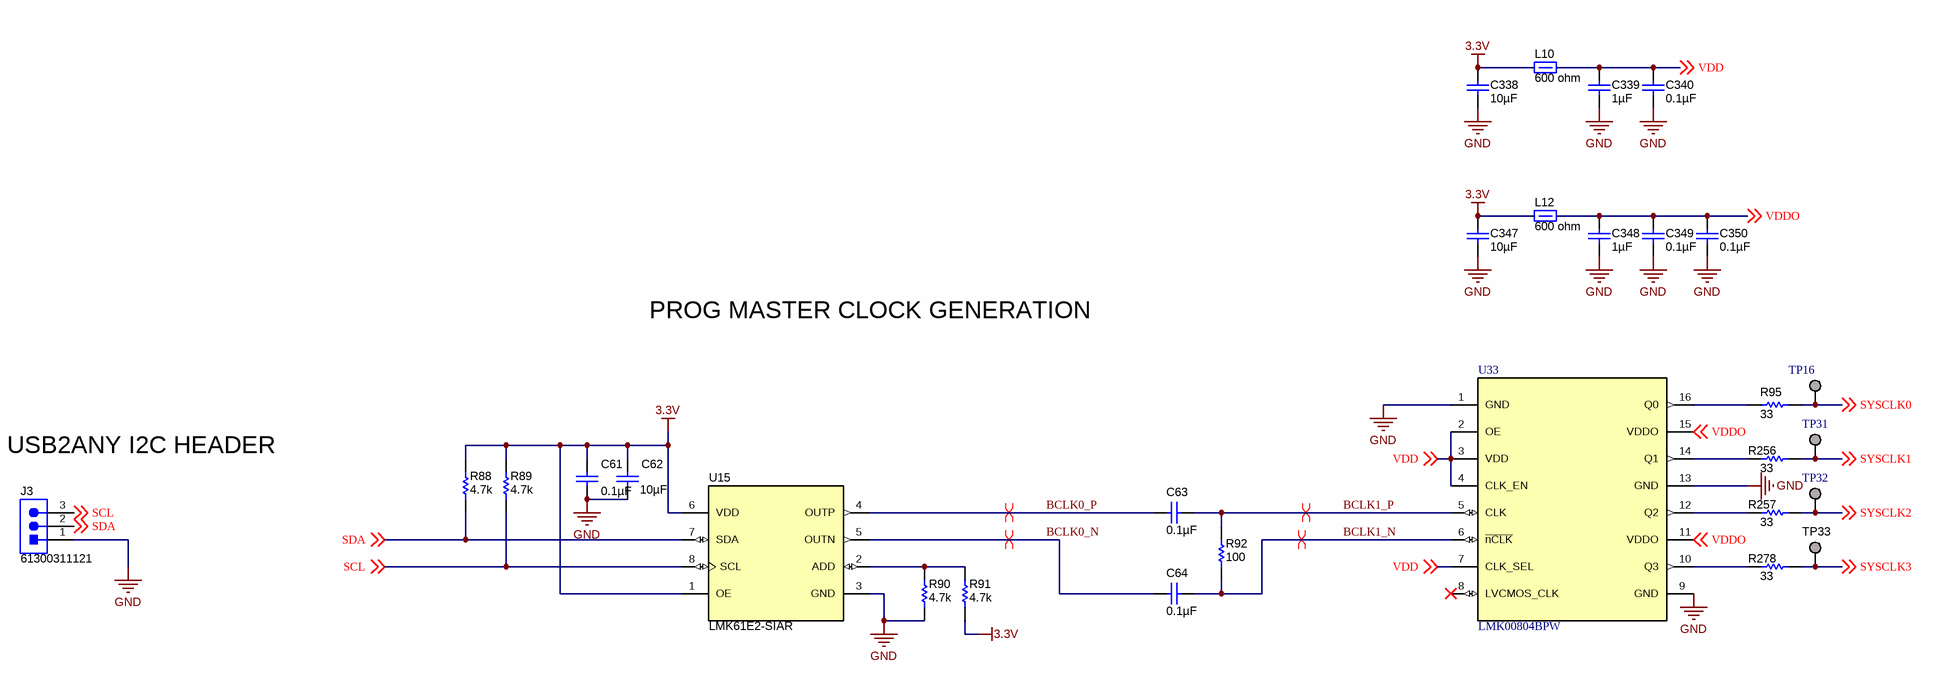
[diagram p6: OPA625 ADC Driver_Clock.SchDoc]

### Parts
C61  ValueDisplayed: 0.1µF  [0603]  (hidden comment: C0603C104J3RACTU)
C62  ValueDisplayed: 10µF  [0603_120]  (hidden comment: ZRB18AD71A106KE01L)
C63  ValueDisplayed: 0.1µF  [0402]  (hidden comment: GRM155R61E104KA87D)
C64  ValueDisplayed: 0.1µF  [0402]  (hidden comment: GRM155R61E104KA87D)
C338  ValueDisplayed: 10µF  [0805_HV]  (hidden comment: GRM21BR71A106KE51L)
C339  ValueDisplayed: 1µF  [0603]  (hidden comment: GRM188R71E105KA12D)
C340  ValueDisplayed: 0.1µF  [0402]  (hidden comment: GRM155R71C104KA88D)
C347  ValueDisplayed: 10µF  [0805_HV]  (hidden comment: GRM21BR71A106KE51L)
C348  ValueDisplayed: 1µF  [0603]  (hidden comment: GRM188R71E105KA12D)
C349  ValueDisplayed: 0.1µF  [0402]  (hidden comment: GRM155R71C104KA88D)
C350  ValueDisplayed: 0.1µF  [0402]  (hidden comment: GRM155R71C104KA88D)
J3  61300311121  [WURTH_61300311121]
L10  value 600 ohm  [0805_HV]  (hidden comment: MPZ2012S601A)
L12  value 600 ohm  [0805_HV]  (hidden comment: MPZ2012S601A)
R88  ValueDisplayed: 4.7k  [0402]  (hidden comment: CRCW04024K70JNED)
R89  ValueDisplayed: 4.7k  [0402]  (hidden comment: CRCW04024K70JNED)
R90  ValueDisplayed: 4.7k  [0402]  (hidden comment: CRCW04024K70JNED)
R91  ValueDisplayed: 4.7k  [0402]  (hidden comment: CRCW04024K70JNED)
R92  ValueDisplayed: 100  [0402]  (hidden comment: CRCW0402100RJNED)
R95  ValueDisplayed: 33  [0402]  (hidden comment: CRCW040233R0JNED)
R256  ValueDisplayed: 33  [0402]  (hidden comment: CRCW040233R0JNED)
R257  ValueDisplayed: 33  [0402]  (hidden comment: CRCW040233R0JNED)
R278  ValueDisplayed: 33  [0402]  (hidden comment: CRCW040233R0JNED)
TP16  Pogo Pad  [PogoPad]  (value not drawn)  (no BOM)
TP31  Pogo Pad  [PogoPad]  (value not drawn)  (no BOM)
TP32  Pogo Pad  [PogoPad]  (value not drawn)  (no BOM)
TP33  Pogo Pad  [PogoPad]  (value not drawn)  (no BOM)
U15  LMK61E2-SIAR  [SIA0008B]
U33  LMK00804BPW  [PW0016A_N]

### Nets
3.3V: C61.1 C62.1 C338.1 C347.1 L10.2 L12.2 R88.2 R89.2 R91.1 U15.1(OE) U15.6(VDD)
GND: C61.2 C62.2 C338.2 C339.2 C340.2 C347.2 C348.2 C349.2 C350.2 J3.1 R90.1 U15.3(GND) U33.1(GND) U33.9(GND) U33.13(GND)
BCLK0_N: C64.1 U15.5(OUTN)
BCLK0_P: C63.1 U15.4(OUTP)
BCLK1_N: C64.2 R92.1 U33.6(~{nCLK})
BCLK1_P: C63.2 R92.2 U33.5(CLK)
SCL: J3.3 R89.1 U15.8(SCL) ; off-sheet SCL
SDA: J3.2 R88.1 U15.7(SDA) ; off-sheet SDA
SYSCLK0: R95.2 TP16.1 ; off-sheet SYSCLK0
SYSCLK1: R256.2 TP31.1 ; off-sheet SYSCLK1
SYSCLK2: R257.2 TP32.1 ; off-sheet SYSCLK2
SYSCLK3: R278.2 TP33.1 ; off-sheet SYSCLK3
VDD: C339.1 C340.1 L10.1 U33.2(OE) U33.3(VDD) U33.4(CLK_EN) U33.7(CLK_SEL) ; off-sheet VDD
VDDO: C348.1 C349.1 C350.1 L12.1 U33.11(VDDO) U33.15(VDDO) ; off-sheet VDDO
NetR90_2: R90.2 R91.2 U15.2(ADD)
NetR95_1: R95.1 U33.16(Q0)
NetR256_1: R256.1 U33.14(Q1)
NetR257_1: R257.1 U33.12(Q2)
NetR278_1: R278.1 U33.10(Q3)

Not connected (* = marked no-connect by the designer): U33 8(LVCMOS_CLK)*

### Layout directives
differential pair: BCLK0_N, BCLK0_P, BCLK1_N, BCLK1_P

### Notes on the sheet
- PROG MASTER CLOCK GENERATION
- USB2ANY I2C HEADER

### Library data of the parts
C61 = C0603C104J3RACTU: as C84 on sheet OPA625 ADC Driver_OPA625 ADC Driver
C62 = ZRB18AD71A106KE01L: CAP, CERM, 10 µF, 10 V, +/- 10%, X7T, 0603; Manufacturer: MuRata; Polarized: N; CompType: Capacitor; Value: 10uF; U/M: EA; Cap_F: 0.00001; Tolerance_%: 10; Value1: Unknown; Value2: 10V; TaMin_C: -55; TaMax_C: 125; Cap_Case: 0603; AEC Category: Q200
C63 C64 = GRM155R61E104KA87D: CAP, CERM, 0.1 µF, 25 V, +/- 10%, X5R, 0402; Manufacturer: MuRata; Polarized: N; CompType: Capacitor; Value: 0.1uF; U/M: EA; Cap_F: 0.0000001; Tolerance_%: 10; Value1: Unknown; VDC_V: 25; Value2: 25V; TaMin_C: -55; TaMax_C: 85; AEC Category: Q200
C338 C347 = GRM21BR71A106KE51L: as C284 on sheet OPA625 ADC Driver_OPA625 ADC Driver
C339 C348 = GRM188R71E105KA12D: as C318 on sheet OPA625 ADC Driver_OPA625 ADC Driver
C340 C349 C350 = GRM155R71C104KA88D: as C94 on sheet OPA625 ADC Driver_OPA625 ADC Driver
J3 = 61300311121: Header, 2.54 mm, 3x1, Gold, TH; Manufacturer: Wurth Elektronik eiSos; SymbolCreator: a0799628; U/M: EA
L10 L12 = MPZ2012S601A: as L6-L9 on sheet OPA625 ADC Driver_OPA625 ADC Driver
R88-R91 = CRCW04024K70JNED: RES, 4.7 k, 5%, 0.063 W, 0402; Manufacturer: Vishay-Dale; CompType: Resistor; Value: 4.7k; Res_ohm: 4700; Value_Code: 4k70; Tolerance_%: 5; Power_W: 0.063; Value2: 0.063W; VDC_V: 50; TempCo: 200 ppm/C; EIA_Code: E24; U/M: EA; AEC Category: Q200
R92 = CRCW0402100RJNED: RES, 100, 5%, 0.063 W, 0402; Manufacturer: Vishay-Dale; CompType: Resistor; Value: 100; Value_Code: 100R; Tolerance_%: 5; Power_W: 0.063; Value2: 0.063W; VDC_V: 50; TempCo: 200 ppm/C; EIA_Code: E24; U/M: EA; AEC Category: Q200
R95 R256 R257 R278 = CRCW040233R0JNED: RES, 33, 5%, 0.063 W, 0402; Manufacturer: Vishay-Dale; CompType: Resistor; Value: 33; Value_Code: 33R0; Tolerance_%: 5; Power_W: 0.063; Value2: 0.063W; VDC_V: 50; TempCo: 200 ppm/C; EIA_Code: E24; U/M: EA; AEC Category: Q200
TP16 TP31-TP33 = PogoPad: as TP1 on sheet OPA625 ADC Driver_OPA625 ADC Driver
U15 = LMK61E2-SIAR: Ultra-Low Jitter Programmable Oscillator with Internal EEPROM, SIA0008B; Alternate PartNumber: LMK61E2-SIAT; Manufacturer: Texas Instruments; SymbolCreator: Altium; CompType: IC; U/M: EA
U33 = LMK00804BPW: Low Skew, 1-to-4 Multiplexed Differential/LVCMOS-to-LVCMOS/TTL Fanout Buffer, PW0016A; Manufacturer: Texas Instruments; SymbolCreator: a0411947; SizeArea_mm2: 32; SizeAreaWB_mm2: 58.8; SizeX_mm: 6.4; SizeY_mm: 5; SizeZ_mm: 1.2; CompType: IC; U/M: EA

## Sheet OPA625 ADC Driver_Hardware.SchDoc
size 431 x 279 mm; Date: Not shown in title block; ApprovedBy: Not shown in title block; CheckedBy: Not shown in title block; Author: Not shown in title block; CompanyName: Not shown in title block; Engineer: Not shown in title block; Organization: Not shown in title block; Address1: Not shown in title block; Address2: Not shown in title block; Address3: Not shown in title block; Address4: Not shown in title block; DocumentNumber: 8; Revision: Use project parameter SCH_Rev; SheetNumber: 8; SheetTotal: 8; PageSetup: Record=PageOptions¦CenterHorizontal=True¦CenterVertical=True¦PrintScale=1.00¦XCorrection=1.00¦YCorrection=1.00¦PrintKind=0¦BorderSize=5000000¦LeftOffset=0¦BottomOffset=0¦Orientation=2¦PaperLength=1000¦PaperWidth=1000¦Scale=100¦PaperSource=15¦PrintQuality=600¦MediaType=1¦DitherType=10¦PaperKind=Letter¦PrintScaleMode=1
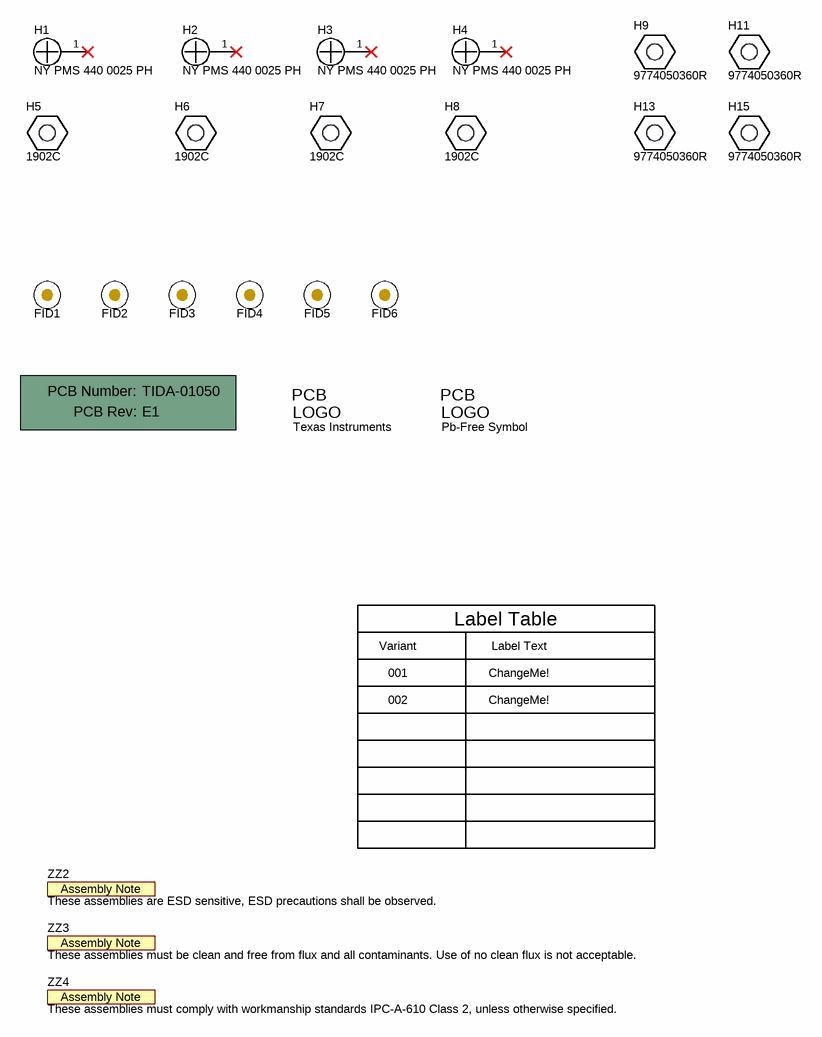
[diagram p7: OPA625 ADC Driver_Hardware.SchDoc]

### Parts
!PCB  Printed Circuit Board  (value not drawn)  (mechanical)
FID1  Fiducial  [Fiducial10-20]  (value not drawn)
FID2  Fiducial  [Fiducial10-20]  (value not drawn)
FID3  Fiducial  [Fiducial10-20]  (value not drawn)
FID4  Fiducial  [Fiducial10-20]  (value not drawn)
FID5  Fiducial  [Fiducial10-20]  (value not drawn)
FID6  Fiducial  [Fiducial10-20]  (value not drawn)
H1  NY PMS 440 0025 PH  [NY PMS 440 0025 PH]
H2  NY PMS 440 0025 PH  [NY PMS 440 0025 PH]
H3  NY PMS 440 0025 PH  [NY PMS 440 0025 PH]
H4  NY PMS 440 0025 PH  [NY PMS 440 0025 PH]
H5  1902C  [Keystone_1902C]
H6  1902C  [Keystone_1902C]
H7  1902C  [Keystone_1902C]
H8  1902C  [Keystone_1902C]
H9  9774050360R  [Wurth_WA-SMSI]
H11  9774050360R  [Wurth_WA-SMSI]
H13  9774050360R  [Wurth_WA-SMSI]
H15  9774050360R  [Wurth_WA-SMSI]
Logo1  Texas Instruments  [TI_Stacked_Overlay_Small]  (no BOM)
Logo2  Pb-Free Symbol  [Pb-Free_Overlay_Small]  (no BOM)
ZZ2  These assemblies are ESD sensitive, ESD precautions shall be observed.  [AssemblyNote]  (no BOM)
ZZ3  These assemblies must be clean and free from flux and all contaminants. Use of no clean flux is not acceptable.  [AssemblyNote]  (no BOM)
ZZ4  These assemblies must comply with workmanship standards IPC-A-610 Class 2, unless otherwise specified.  [AssemblyNote]  (no BOM)

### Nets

Not connected (* = marked no-connect by the designer): H1 1*; H2 1*; H3 1*; H4 1*

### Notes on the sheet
- Variant
- Label Table
- Label Text
- 001
- 002
- ChangeMe!

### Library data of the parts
!PCB = PCB: Manufacturer: Any; PartNumber: TIDA-01050; SymbolCreator: a0412235
FID1-FID6 = Fiducial: Fiducial mark.  There is nothing to buy or mount.; SymbolCreator: codlsc
H1-H4 = NY PMS 440 0025 PH: Machine Screw, Round, #4-40 x 1/4, Nylon, Philips panhead; Manufacturer: B&F Fastener Supply; CompType: Hardware; SymbolCreator: codlsc; U/M: EA
H5-H8 = 1902C: Standoff, Hex, 0.5"L #4-40 Nylon; Manufacturer: Keystone; CompType: Hardware
H9 H11 H13 H15 = 9774050360R: ROUND STANDOFF M3 STEEL 5MM; Manufacturer: Wurth Elektronik; SymbolCreator: a0412235
Logo1 = TI_Logo: Texas Instrument Corporate Signature; SymbolCreator: codlsc
Logo2 = Pb-Free: SymbolCreator: a0412235
ZZ2-ZZ4 = AssemblyNote: SymbolCreator: codlsc

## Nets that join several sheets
3.3V: OPA625 ADC Driver_Power (8 pins), OPA625 ADC Driver_OPA625 ADC Driver (14 pins), OPA625 ADC Driver_Clock (11 pins)
5V: OPA625 ADC Driver_Power (7 pins), OPA625 ADC Driver_OPA625 ADC Driver (20 pins)
+18V: OPA625 ADC Driver_Power (7 pins), OPA625 ADC Driver_OPA625 ADC Driver (8 pins)
-18V: OPA625 ADC Driver_Power (6 pins), OPA625 ADC Driver_OPA625 ADC Driver (8 pins)
AGND: OPA625 ADC Driver_Power (6 pins), OPA625 ADC Driver_OPA625 ADC Driver (85 pins)
GND: OPA625 ADC Driver_Power (118 pins), OPA625 ADC Driver_Connectors (34 pins), OPA625 ADC Driver_OPA625 ADC Driver (12 pins), OPA625 ADC Driver_Clock (15 pins)
VEE: OPA625 ADC Driver_Power (J34.2), OPA625 ADC Driver_OPA625 ADC Driver (R248.2 R250.2 R252.2)
CONVST: OPA625 ADC Driver_Connectors (R67.1 R78.1), OPA625 ADC Driver_OPA625 ADC Driver (6 pins)
CSn: OPA625 ADC Driver_Connectors (R68.1 R79.1), OPA625 ADC Driver_OPA625 ADC Driver (UADS1.24 UADS2.24)
RVS_DIF: OPA625 ADC Driver_Connectors (R71.1), OPA625 ADC Driver_OPA625 ADC Driver (UADS1.21)
RVS_SE: OPA625 ADC Driver_Connectors (R82.1), OPA625 ADC Driver_OPA625 ADC Driver (UADS2.21)
SCLK: OPA625 ADC Driver_Connectors (R69.1 R80.1), OPA625 ADC Driver_OPA625 ADC Driver (UADS1.23 UADS2.23)
SDI: OPA625 ADC Driver_Connectors (R66.1 R77.1), OPA625 ADC Driver_OPA625 ADC Driver (UADS1.22 UADS2.22)
SDO0_DIF: OPA625 ADC Driver_Connectors (R72.1), OPA625 ADC Driver_OPA625 ADC Driver (R235.2)
SDO0_SE: OPA625 ADC Driver_Connectors (R83.1), OPA625 ADC Driver_OPA625 ADC Driver (R226.2)
SDO1_DIF: OPA625 ADC Driver_Connectors (R73.1), OPA625 ADC Driver_OPA625 ADC Driver (R234.2)
SDO1_SE: OPA625 ADC Driver_Connectors (R84.1), OPA625 ADC Driver_OPA625 ADC Driver (R225.2)
SDO2_DIF: OPA625 ADC Driver_Connectors (R74.1), OPA625 ADC Driver_OPA625 ADC Driver (R233.2)
SDO2_SE: OPA625 ADC Driver_Connectors (R85.1), OPA625 ADC Driver_OPA625 ADC Driver (R240.2)
SDO3_DIF: OPA625 ADC Driver_Connectors (R75.1), OPA625 ADC Driver_OPA625 ADC Driver (R232.2)
SDO3_SE: OPA625 ADC Driver_Connectors (R86.1), OPA625 ADC Driver_OPA625 ADC Driver (R223.2)
SRESETn: OPA625 ADC Driver_Connectors (R65.1 R76.1), OPA625 ADC Driver_OPA625 ADC Driver (UADS1.2 UADS2.2)
SYSCLK0: OPA625 ADC Driver_OPA625 ADC Driver (U18.2 U31.2), OPA625 ADC Driver_Clock (R95.2 TP16.1)
SYSCLK1: OPA625 ADC Driver_Connectors (R70.1 R81.1), OPA625 ADC Driver_Clock (R256.2 TP31.1)

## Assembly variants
001: not fitted C316 C317 FID1 FID2 FID3 FID4 FID5 FID6 R11 R12 R15 R17 R18 R20 R21 R24 R26 R27 R29 R30 R31 R33 R34 R90 R96 R106 R129 R130 R131 R134 R181 R182 R241 R242 R243 R244 R245 R249 R251 R253 R255 R260 R263 R277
